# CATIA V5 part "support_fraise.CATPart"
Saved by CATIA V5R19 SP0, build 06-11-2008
Part number: support_fraise
Bounding box of the stored display mesh (mm): x -212.5 to 0, y 0 to 60, z -30 to 30
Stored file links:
  C:\Users\Alex\IFMA\2A\IAO\Modélisation\support_fraise.CATPart
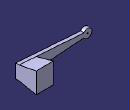
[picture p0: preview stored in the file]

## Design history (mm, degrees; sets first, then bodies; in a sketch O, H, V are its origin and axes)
Parameters
  hauteur_support_fraise = 50 mm
Body1 (main body)
  Sketch1 on zx-plane, origin (0, 0, 0), H (-1, 0, 0), V (0, 0, 1)
    line L1 (0, 0) -> (0, 20)
    point P2 (200, 0)
    arc A1 centre (200, 0) radius 12.5 from (212.5, 0) to (189.1747, 6.25) ccw
    line L2 (0, 20) -> (189.1747, 6.25)
    line L3 (0, 0) -> (212.5, 0)
    radius A1 = 12.5
    length L1 = 20
    distance P2 L1 = 200
    vertical: L1 V
    coincidence: P2 H
    horizontal: L3 H
  Pad1: profile Sketch1, direction (0, 1, 0), length 10
  Mirror1: of the body so far, about face of Pad1 from Sketch1.L3
  Sketch2 on face of Pad1, origin (-49.7499, 10, 0.4539), H (1, 0, 0), V (0, 0, -1)
    point P1 (-150.2501, 0.4539)
    reference projected arc E1 centre (-150.2501, 0.4539) radius 12.5 from (-162.7501, 0.4539) to (-139.4248, -5.7961) ccw from edge [face of Pad1 from Sketch1.A1 | face of Pad1]
    concentricity: P1 E1
  Hole1: placed by Sketch2, at (-200, 10, 0) direction (0, -1, 0), diameter 3, depth 10
  Sketch3 on face of Pad1, origin (0, 10, 0), H (-1, 0, 0), V (0, 0, 1)
    point P1 (0, 20)
    line L1 (0, 20) -> (0, -20)
    point P2 (0, -20)
    line L2 (0, -20) -> (50, -16.3658)
    point P3 (50, -16.3658)
    line L3 (50, -16.3658) -> (50, 16.3658)
    point P4 (50, 16.3658)
    line L4 (50, 16.3658) -> (0, 20)
    reference projected point E1 (0, 20) from vertex [face of Pad1 from Sketch1.L1 | end face of Pad1 | face of Pad1 from Sketch1.L2]
    reference projected point E2 (0, -20) from vertex [face of Mirror1 | face of Mirror1 | face of Mirror1]
    reference projected line E3 (46.2872, 16.6357) -> (-0.2226, 20.0162) from edge [face of Pad1 from Sketch1.L2 | end face of Pad1]
    reference projected line E4 (46.2872, -16.6357) -> (-0.2226, -20.0162) from edge [face of Mirror1 | face of Mirror1]
    distance L3 L1 = 50
    vertical: L1 V, L3 V
    coincidence: P1 E1, P2 E2, P4 E3, P3 E4
  Plane1: type Offset, Offset 50 {= hauteur_support_fraise}, RefPlane face of Pad1, reversed
  Sketch4 on Plane1, origin (0, 60, 0), H (1, 0, 0), V (0, 0, 1)
    point P1 (0, 30)
    line L1 (0, 30) -> (-50, 30)
    line L2 (-50, 30) -> (-50, -30)
    line L3 (-50, -30) -> (0, -30)
    line L4 (0, -30) -> (0, 30)
    length L4 = 60
    distance H L1 = 30
    length L1 = 50
    coincidence: P1 V
    horizontal: L1 H, L3 H
    vertical: L2 V, L4 V
  Loft1: solid, Sections (Sketch3; Sketch4)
